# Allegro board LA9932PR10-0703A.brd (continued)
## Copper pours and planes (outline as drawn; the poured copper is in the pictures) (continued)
+VCHGR on BOTTOM (solid shape): 96.67,157.9 96.67,154.12 96.34,153.8 86.85,153.8 86.68,153.97 86.68,155.31 93.31,155.31 93.31,155.26 93.32,155.21 93.34,155.16 93.37,155.11 93.4,155.07 93.44,155.03 93.49,155 93.53,154.98 93.58,154.96 93.64,154.96 93.69,154.96 93.74,154.96 93.79,154.98 93.84,155 93.89,155.03 93.93,155.07 93.96,155.11 93.99,155.16 94,155.21 94.02,155.26 94.02,155.31 94.02,155.36 94,155.42 93.99,155.47 93.96,155.51 93.93,155.55 93.89,155.59 93.84,155.62 93.79,155.64 93.74,155.66 93.69,155.67 93.64,155.67 93.58,155.66 93.53,155.64 93.49,155.62 93.44,155.59 93.4,155.55 93.37,155.51 93.34,155.47 93.32,155.42 93.31,155.36 93.31,155.31 86.68,155.31 86.68,155.84 88.05,155.84 88.08,155.84 88.13,155.85 88.18,155.87 88.23,155.89 88.27,155.92 88.31,155.96 88.35,156 88.37,156.05 88.39,156.09 88.4,156.15 88.41,156.2 88.4,156.25 88.39,156.31 88.37,156.35 88.35,156.4 88.31,156.44 88.27,156.48 88.23,156.51 88.18,156.53 88.13,156.55 88.08,156.56 88.05,156.56 86.68,156.56 86.68,158.04 87.06,158.42 96.14,158.42
+VDISPLAY_VCC on TOP (solid shape): 13.33,201.72 13.33,200.34 13.26,200.27 12.2,200.27 12.02,200.44 12.02,201.64 12.15,201.77 13.28,201.77
+VDISPLAY_VCC on TOP (solid shape): 24.77,210.47 24.77,209.16 25.66,208.27 27.58,208.27 28.45,207.4 28.45,205.3 28.19,205.04 27.35,205.04 27.14,205.25 27.14,205.8 26.69,206.25 26.24,206.25 23.86,208.62 22.67,208.62 22.52,208.77 22.52,210.74 22.69,210.92 24.32,210.92
+VDISPLAY_VCC on BOTTOM (solid shape): 23.4,210.65 23.4,209.76 25.27,207.89 25.27,206.82 25.07,206.62 24.09,206.62 23.97,206.74 23.29,206.74 22.52,207.51 22.52,210.72 22.67,210.88 23.18,210.88
+VDISPLAY_VCC on IN2 (solid shape): 13.88,201.61 13.88,200.69 13.73,200.54 12.1,200.54 11.94,200.7 11.94,201.53 12.13,201.72 13.77,201.72
+VDISPLAY_VCC on IN2 (solid shape): 24.3,210.92 24.32,210.91 24.34,210.9 24.77,210.47 24.77,209.16 25.66,208.27 27.58,208.27 28.45,207.4 28.45,205.3 28.19,205.04 27.35,205.04 27.14,205.25 27.14,205.8 26.69,206.25 26.24,206.25 25.42,207.07 23.65,207.07 23.31,206.73 22.29,206.73 22.09,206.92 22.09,208.49 22.51,208.9 22.51,210.71 22.52,210.72 22.52,210.74 22.69,210.92
+VGA_B+ on TOP (solid shape): 17.08,157.98 17.08,155.5 16.77,155.18 11.24,155.18 10.86,155.57 10.86,157.03 11.18,157.34 15.37,157.34 16.16,158.14 16.92,158.14
+VGA_B+ on BOTTOM (solid shape): 4.89,162.49 4.89,161.47 5.08,161.28 6.73,161.28 7.69,160.33 7.69,156.01 8.26,155.44 10.54,155.44 10.86,155.76 10.86,157.09 11.11,157.34 15.56,157.34 15.94,157.72 15.94,159.44 16.13,159.63 16.77,159.63 16.96,159.44 16.96,154.61 13.08,150.74 4.89,150.74 3.08,152.55 3.08,154.64 3.05,154.68 3.05,156.01 4.28,157.24 4.29,157.25 4.32,157.28 4.32,157.9 4.33,157.92 4.84,157.92 4.84,158.62 4.33,158.62 4.33,159.12 4.84,159.12 4.84,159.82 4.33,159.82 4.33,161.01 4.13,161.22 4.13,162.49 4.19,162.55 4.83,162.55
+VGA_PCIE on TOP (solid shape): 86.78,128.82 88.36,128.82 88.49,128.69 88.49,127.99 88.43,127.93 86.29,127.93 85.57,128.66 85.57,129.61 85.69,129.73 85.86,129.73
+VGA_PCIE on BOTTOM (solid shape): 101.67,140.71 101.67,139.72 101.73,139.72 101.73,139.71 102.24,139.71 102.24,139.46 101.73,139.46 101.73,139.43 101.72,139.43 101.72,138.93 101.73,138.93 101.73,138.91 102.24,138.91 102.24,138.67 101.67,138.67 101.67,136.64 101.13,136.1 101.11,136.1 101.01,136.01 99.06,136.01 98.29,136.78 98.29,139.2 98.81,139.72 99.38,139.72 100.55,140.9 101.47,140.9
+VGA_PCIE on IN2 (solid shape): outline of 93 points within 74.77,129.07 79.16,135.91
+VGA_PCIE on VCC: 95.55,127.69 95.1,128.13 85.2,128.13 84.69,128.64 77.26,128.64 76.2,129.7 76.2,132.37 75.48,133.09 75.1,133.09 74.93,133.25 74.93,135.27 76.58,136.92 76.58,144.33 82.65,144.33 85,146.61 95.84,146.61 100.14,142.32 100.14,133.89 96.97,130.71 96.97,128.62 96.04,127.69
+VGA_PCIEP on TOP (solid shape): 105.79,139.75 105.79,138.17 105.48,137.85 103.91,137.85 103.9,137.86 103.9,140 103.91,140.01 105.54,140.01
+VGA_PCIEP on BOTTOM (solid shape): 108.97,140.93 108.97,138.35 108.78,138.16 105.92,138.16 105.6,137.85 104.89,137.85 104.89,137.85 103.83,137.85 103.83,137.85 101.98,137.85 101.86,137.98 101.86,138.53 102.37,138.53 102.37,139.03 101.86,139.03 101.86,139.33 102.37,139.33 102.37,139.83 101.86,139.83 101.86,140.26 101.92,140.33 103.44,140.33 103.76,140.01 103.83,140.01 104.89,140.01 104.9,140.01 106.23,141.34 108.55,141.34
-DCIN_JACK on BOTTOM (solid shape): 21.52,182.6 23.16,182.6 23.17,182.61 23.73,182.61 23.73,183.12 24.22,183.12 24.22,182.61 24.93,182.61 24.93,183.12 25.42,183.12 25.42,182.61 26.23,182.61 26.23,180.39 25.53,179.7 21.96,179.7 20.48,181.18 13.44,181.18 13.35,181.27 13.35,183.48 13.47,183.6 20.52,183.6
BOOT on TOP (solid shape): 55.96,164.02 55.96,162.97 55.89,162.9 55.41,162.9 54.99,162.49 54.04,162.49 53.85,162.68 52.77,162.68 52.71,162.74 52.71,162.87 52.77,162.93 54.81,162.93 55.15,163.27 55.15,163.99 55.24,164.07 55.49,164.07 55.49,164.07 55.91,164.07
BOOT1 on BOTTOM (solid shape): 126.24,142.04 126.24,141.34 126.27,141.31 126.27,141.29 126.33,141.13 126.49,141.07 126.51,141.07 127.32,140.26 127.32,139.25 127.26,139.18 126.42,139.18 126.32,139.28 126.32,140.93 126.24,141.02 125.99,141.28 125.99,142.04 126.05,142.1 126.18,142.1
BOOT1_1_VGA on TOP (solid shape): 27.31,154.3 27.31,153.6 27.94,152.96 27.94,152.39 27.81,152.26 27.12,152.26 26.54,152.83 26.54,154.23 26.67,154.36 27.24,154.36
BOOT1_VGA on TOP (solid shape): 27.94,151.63 27.94,150.99 27.81,150.87 27.56,150.87 27.5,150.8 27.43,150.8 27.43,150.74 26.73,150.04 26.7,150.03 26.69,150.04 26.5,150.06 26.33,149.98 25.21,149.98 25.15,150.04 25.15,150.1 25.27,150.23 26.16,150.23 26.74,150.8 26.74,151.5 26.93,151.69 27.88,151.69
BOOT2 on BOTTOM (solid shape): 122.56,143.18 123.45,143.18 123.51,143.12 123.51,143.06 123.45,142.99 122.62,142.99 122.37,142.74 121.49,142.74 121.48,142.74 121.29,142.55 121.29,142.54 121.29,142.29 121.22,142.23 120.72,142.23 120.65,142.29 120.65,143.18 120.72,143.25 122.49,143.25
BOOT2_2_VGA on TOP (solid shape): 21.46,154.74 21.46,154.17 21.4,154.1 19.31,154.1 19.24,154.17 19.24,154.74 19.37,154.87 21.34,154.87
BOOT2_VGA on TOP (solid shape): 20.26,153.41 20.26,151.88 20.45,151.69 20.47,151.67 21.42,151.67 21.48,151.61 21.48,150.74 21.42,150.68 21.33,150.68 20.96,151.06 20.13,151.06 19.31,151.88 19.31,153.41 19.37,153.47 20.19,153.47
BOOT_1.35V on TOP (solid shape): 173.36,87.56 173.36,86.99 173.58,86.76 174.4,86.76 174.5,86.67 175.58,86.67 175.64,86.6 175.64,86.54 175.58,86.48 172.91,86.48 172.4,86.99 172.4,87.49 172.53,87.62 173.29,87.62
BOOT_D on TOP (solid shape): 57.06,165.41 57.06,164.93 58.26,163.72 58.26,161.69 58.17,161.6 57.09,161.6 56.57,162.12 56.57,164.33 56.33,164.58 56.33,165.28 56.48,165.44 57.02,165.44
BQ24715_REGN on TOP (solid shape): 56.32,162.45 56.32,160 56.19,159.86 53.99,159.86 53.6,160.25 53.6,161.78 53.21,162.17 52.77,162.17 52.71,162.23 52.71,162.42 52.77,162.49 53.79,162.49 53.98,162.3 54.98,162.3 55.32,162.63 56.14,162.63
BST_3V on TOP (solid shape): 198.75,36.95 198.75,36.16 198.82,36.1 198.82,36.1 199.13,35.78 199.14,35.78 199.21,35.71 199.65,35.71 200.22,35.14 200.22,34.15 200.13,34.06 199.25,34.06 199.2,34.11 199.2,35.03 198.54,35.69 198.54,36.94 198.59,36.99 198.72,36.99
BST_5V on TOP (solid shape): 200.19,41.91 200.19,40.77 199.91,40.49 199.13,40.49 198.75,40.1 198.75,39.26 198.69,39.19 198.58,39.19 198.55,39.22 198.55,40.52 198.88,40.85 198.88,40.85 199,40.96 199,40.97 199.08,41.05 199.08,42.01 199.12,42.05 200.04,42.05
BST_+1.05VSP on TOP (solid shape): 175.13,94.73 175.13,94.54 174.75,94.16 174.75,92.51 174.69,92.45 174.18,92.45 174.12,92.51 174.12,94.48 174.44,94.8 175.07,94.8
CHAGER_SRC on BOTTOM (solid shape): outline of 158 points within 56.9,151.93 67.46,165.92
CHG_LGATE on TOP (solid shape): 64.14,161.98 64.14,160.9 63.95,160.71 63.12,160.71 62.74,161.09 62.74,161.98 62.93,162.17 63.95,162.17
CHG_LGATE on TOP (solid shape): 52.64,162.04 52.64,161.92 52.83,161.72 53.09,161.72 53.28,161.53 53.28,160.77 53.15,160.65 52.83,160.65 52.39,161.09 52.39,162.04 52.45,162.11 52.58,162.11
CHG_LGATE on TOP (solid shape): 64.07,156.27 64.07,155.36 63.79,155.09 63.79,151.84 63.62,151.67 62.95,151.67 62.86,151.76 62.86,155.16 62.8,155.21 62.8,156.25 62.97,156.42 63.93,156.42
CHG_LGATE on IN2 (solid shape): 64.01,161.41 64.01,155.3 63.87,155.15 62.96,155.15 62.8,155.31 62.8,160.45 62.61,160.65 61.91,160.65 61.53,161.03 61.53,161.66 61.6,161.72 63.69,161.72
CHG_LGATE on IN2 (solid shape): 54.51,161.72 54.68,161.69 54.84,161.72 57.09,161.72 57.34,161.47 57.34,160.9 57.02,160.58 52.96,160.58 52.71,160.84 52.71,161.47 52.96,161.72
CHG_PHASE on TOP (solid shape): 55.75,165.41 55.75,164.52 55.44,164.2 55.06,164.2 54.93,164.07 54.93,163.82 54.8,163.69 53.92,163.69 53.92,163.69 52.77,163.69 52.71,163.76 52.71,163.88 52.77,163.95 53.85,163.95 55.06,165.15 55.06,165.41 55.12,165.47 55.69,165.47
CHG_PHASE on TOP (solid shape): outline of 97 points within 64.77,153.69 72.14,165.98
CHG_PHASE on BOTTOM (solid shape): 74.8,165.28 74.8,157.47 74.8,157.47 74.8,156.75 74.3,156.25 69.9,156.25 69.67,156.48 69.67,156.9 69.42,157.15 68.43,157.15 68.25,157.33 68.25,160.17 68.42,160.33 69.53,160.33 69.79,160.59 69.79,162.23 69.28,162.74 68.45,162.74 68.26,162.93 68.26,165.72 68.45,165.91 74.17,165.91
CHG_PHASE on IN2 (solid shape): 56.01,164.46 56.01,163.95 55.76,163.69 53.98,163.69 53.91,163.76 53.91,164.07 53.98,164.14 54.55,164.14 54.99,164.58 55.88,164.58
CHG_PHASE on IN2 (solid shape): 70.22,164.32 70.22,163.45 70.08,163.31 68.73,163.31 68.59,163.45 68.59,164.28 68.77,164.46 70.08,164.46
CHG_UGATE on BOTTOM (solid shape): 69.53,156.33 69.53,155.29 69.35,155.11 68.05,155.11 67.91,155.25 67.91,156.05 68.38,156.52 69.34,156.52
CHG_UGATE on BOTTOM (solid shape): 69.6,161.88 69.6,161 69.43,160.84 68.65,160.84 68.26,161.22 68.26,161.92 68.45,162.11 69.37,162.11
CHG_UGATE on IN2 (solid shape): 69.57,161.18 69.57,155.38 69.28,155.09 68.03,155.09 67.89,155.22 67.89,156.12 68.2,156.43 68.2,160.33 68.07,160.45 67.38,160.45 67.18,160.65 67.18,161.09 67.44,161.34 69.41,161.34
CHG_UGATE on IN2 (solid shape): 54.1,163.55 54.2,163.57 54.59,163.57 54.69,163.55 54.78,163.57 55.73,163.57 55.82,163.57 56.07,163.31 56.07,162.87 55.95,162.74 55.25,162.74 54.87,163.12 53.91,163.12 53.85,163.19 53.85,163.44 53.98,163.57
CPU_B+ on TOP (solid shape): 123.06,140.28 123.26,140.22 123.45,140.28 124.18,140.28 124.61,139.85 127.09,139.85 130.97,135.97 133.95,135.97 134.48,135.44 134.48,132.48 134.09,132.09 130.27,132.09 128.76,133.59 128.76,134.56 126.05,137.27 118.5,137.27 118.17,136.95 118.17,135.25 118.13,135.21 114.05,135.21 113.41,135.85 113.41,139.71 113.98,140.28
CPU_B+ on BOTTOM (solid shape): 131.13,136.55 134.84,136.55 135,136.39 135,132.03 134.75,131.78 128.8,131.78 128.64,131.94 128.64,136.57 128.97,136.9 130.78,136.9
CPU_B+ on BOTTOM (solid shape): outline of 231 points within 98.13,131.9 118.24,157.72
CPU_B+ on IN3 (solid shape): outline of 121 points within 113.41,132.01 133.13,139.79
DH_1.35V on TOP (solid shape): 161.61,88 161.61,87.11 161.42,86.92 160.46,86.92 160.25,87.13 160.25,88.05 160.44,88.24 161.37,88.24
DH_1.35V on TOP (solid shape): 174.75,87.11 175.58,87.11 175.64,87.05 175.64,86.92 175.58,86.86 174.5,86.86 174.44,86.92 173.74,86.92 173.61,87.05 173.61,87.64 173.72,87.75 174.12,87.75
DH_1.35V on IN1 (solid shape): 161.86,88.19 161.86,87.3 161.48,86.92 160.62,86.92 160.5,87.05 160.5,88.16 160.85,88.51 161.55,88.51
DH_1.35V on IN1 (solid shape): 174.56,87.24 174.56,87.11 174.44,86.99 171.96,86.99 171.39,87.56 171.39,87.87 171.58,88.06 173.74,88.06
DL_1.35V on TOP (solid shape): 166.88,87.11 166.88,86.22 166.69,86.03 165.8,86.03 165.61,86.22 165.61,87.18 165.74,87.3 166.69,87.3
DL_1.35V on TOP (solid shape): 175.8,88.6 175.93,88.6 176.02,88.51 176.02,87.75 175.96,87.68 175.9,87.68 174.75,88.83 174.75,89.14 174.94,89.33 175.07,89.33
DL_1.35V on IN4 (solid shape): 167.07,88.7 167.07,87.11 166.75,86.79 165.93,86.79 165.74,86.99 165.74,88.7 165.99,88.95 166.82,88.95
DL_1.35V on IN4 (solid shape): 175.64,88.83 175.64,88.51 175.52,88.38 173.67,88.38 173.48,88.57 173.48,89.21 173.67,89.4 175.07,89.4
EXT_MIC on TOP (solid shape): 286.01,154.68 286.01,153.92 286.22,153.71 287.14,153.71 287.32,153.53 288.95,153.53 289.04,153.63 289.8,153.63 290.25,153.18 290.25,152.76 289.88,152.39 286.51,152.39 286.2,152.71 285.37,152.71 284.78,153.29 284.58,153.29 284.55,153.3 284.48,153.38 284.48,153.92 284.86,153.92 285.14,154.2 285.14,154.59 285.3,154.75 285.94,154.75
EXT_MIC on IN1 (solid shape): 291.07,154.26 291.07,153.79 289.72,152.44 289.43,152.44 288.72,153.14 288.72,153.27 289.15,153.69 289.15,154.18 289.98,155.01 290.32,155.01
INT_SPK_L+ on TOP (solid shape): 273.12,162.8 273.12,161.98 272.92,161.79 272.92,160.39 272.86,160.33 272.73,160.33 272.67,160.39 272.67,162.87 272.73,162.93 272.99,162.93
INT_SPK_L+ on TOP (solid shape): 179.19,15.62 179.19,12.79 179.15,12.75 178.15,12.75 178.08,12.82 178.08,13.67 178.25,13.83 178.25,15.6 178.43,15.79 178.48,15.83 178.98,15.83
INT_SPK_L+ on IN4 (solid shape): 179.26,15.67 179.26,13.58 178.94,13.26 178.56,13.26 178.25,13.58 178.25,15.74 178.31,15.8 179.14,15.8
INT_SPK_L+ on IN4 (solid shape): 273.37,162.68 273.37,160.84 273.18,160.65 272.48,160.65 272.23,160.9 272.23,161.92 272.35,162.04 272.35,162.49 272.73,162.87 273.18,162.87
INT_SPK_L- on TOP (solid shape): 180.34,15.55 180.34,13.88 180.66,13.56 180.66,12.79 180.62,12.76 179.55,12.76 179.46,12.85 179.46,15.62 179.64,15.8 180.09,15.8
INT_SPK_L- on TOP (solid shape): 272.42,162.87 272.42,160.39 272.35,160.33 272.23,160.33 272.16,160.39 272.16,161.48 272.16,161.49 272.18,161.6 272.16,161.7 272.16,161.71 272.16,161.92 272.1,161.98 271.72,161.98 271.62,162.08 271.62,162.92 271.7,162.99 272.29,162.99
INT_SPK_L- on IN4 (solid shape): 180.53,15.61 180.53,14.91 180.98,14.47 180.98,14.02 180.6,13.64 180.28,13.64 179.58,14.34 179.58,15.61 179.71,15.74 180.41,15.74
INT_SPK_L- on IN4 (solid shape): 272.1,162.87 272.1,162.59 272.1,162.17 271.92,161.99 271.91,161.98 271.89,161.98 270.45,161.98 270.26,162.17 270.26,162.8 270.45,162.99 271.97,162.99
INT_SPK_R+ on TOP (solid shape): 272.8,165.15 272.8,164.58 272.54,164.33 271.21,164.33 270.89,164.01 270.89,163.57 270.83,163.5 270.7,163.5 270.64,163.57 270.64,164.39 271.59,165.34 272.61,165.34
INT_SPK_R+ on TOP (solid shape): 183.01,15.61 183.01,13.67 182.84,13.5 182.84,12.81 182.81,12.78 181.78,12.78 181.74,12.81 181.74,13.5 182.12,13.88 182.12,14.32 182.12,14.32 182.12,15.61 182.25,15.74 182.88,15.74
INT_SPK_R+ on IN4 (solid shape): 183.07,16.55 183.07,14.79 182.95,14.66 182.31,14.66 182.18,14.79 182.18,16.49 182.33,16.64 182.99,16.64
INT_SPK_R+ on IN4 (solid shape): 272.73,165.22 272.73,164.71 272.54,164.52 272.33,164.52 272.33,164.52 271.09,164.52 270.89,164.71 270.26,164.71 270.13,164.84 270.13,165.34 270.32,165.53 272.42,165.53
INT_SPK_R- on TOP (solid shape): 184.28,15.48 184.28,12.81 184.26,12.78 183.24,12.78 183.21,12.82 183.21,13.42 183.26,13.48 183.26,15.55 183.45,15.74 184.02,15.74
INT_SPK_R- on TOP (solid shape): 272.35,164.01 272.35,163.31 272.29,163.25 271.59,163.25 271.4,163.06 271.4,162.74 271.34,162.68 271.22,162.68 271.19,162.69 271.17,162.73 271.17,163.93 271.32,164.07 272.29,164.07
INT_SPK_R- on IN4 (solid shape): 184.47,16.31 184.47,15.04 184.09,14.66 183.58,14.66 183.39,14.85 183.39,16.33 183.6,16.54 184.23,16.54
INT_SPK_R- on IN4 (solid shape): 270.51,164.26 270.68,164.24 270.86,164.26 270.86,164.26 272.23,164.26 272.35,164.14 272.35,163.38 272.23,163.25 272.08,163.25 270.32,163.25 270.19,163.38 270.19,164.2 270.26,164.26 270.5,164.26
INT_SPKL_L+ on TOP (solid shape): 179.26,12.18 179.26,10.4 179.2,10.34 178.25,10.34 178.06,10.53 178.06,12.25 178.12,12.31 179.14,12.31
INT_SPKL_L+ on BOTTOM (solid shape): 179.71,11.23 179.71,8.82 178.75,8.82 178.75,11.23 178.88,11.36 179.58,11.36
INT_SPKL_L- on TOP (solid shape): 180.72,12.18 180.72,11.48 181.12,11.09 181.12,10.57 180.89,10.34 179.64,10.34 179.55,10.44 179.55,12.21 179.64,12.31 180.6,12.31
INT_SPKL_L- on BOTTOM (solid shape): 180.98,11.23 180.98,8.82 180.09,8.82 180.09,11.23 180.28,11.42 180.79,11.42
INT_SPKR_R+ on TOP (solid shape): 182.88,12.25 182.88,10.66 182.44,10.21 181.8,10.21 181.61,10.4 181.61,12.25 181.68,12.31 182.82,12.31
INT_SPKR_R+ on BOTTOM (solid shape): 182.37,11.23 182.37,8.82 181.36,8.82 181.36,11.17 181.55,11.36 182.25,11.36
INT_SPKR_R- on TOP (solid shape): 184.34,12.19 184.34,11.46 184.66,11.14 184.66,10.53 184.34,10.21 183.39,10.21 183.2,10.4 183.2,12.22 183.24,12.26 184.27,12.26
INT_SPKR_R- on BOTTOM (solid shape): 184.15,11.1 184.15,10.53 183.45,9.83 183.45,8.82 182.63,8.82 182.63,10.47 183.52,11.36 183.9,11.36
LG_3V on TOP (solid shape): 207.3,34.81 207.3,34.45 207.2,34.34 206.38,34.34 205.93,33.9 205.42,33.9 205.23,34.09 205.23,34.79 205.36,34.92 207.2,34.92
LG_3V on TOP (solid shape): 201.52,36.95 201.52,36.41 201.3,36.19 200.47,36.19 200.28,36.38 200.28,36.95 200.05,37.18 199.67,37.18 199.4,37.18 199.35,37.23 199.35,37.38 199.39,37.43 201.04,37.43
LG_5V on TOP (solid shape): 204.73,44.31 204.73,44.12 203.9,43.3 203.9,43.04 203.77,42.92 203.01,42.92 202.88,43.04 202.88,43.68 203.65,44.44 204.6,44.44
LG_5V on TOP (solid shape): 201.3,40.24 201.3,39.43 200.83,38.95 200.44,38.95 200.25,38.76 199.39,38.76 199.35,38.81 199.35,38.99 199.39,39.03 199.9,39.03 200.1,39.23 200.1,40.19 200.53,40.63 200.92,40.63
LG_+1.05VSP on TOP (solid shape): 165.74,100.19 165.74,99.37 165.61,99.24 164.78,99.24 164.66,99.37 164.66,100.26 164.72,100.32 165.61,100.32
LG_+1.05VSP on IN2 (solid shape): 166.94,100.07 166.94,99.24 166.82,99.11 164.91,99.11 164.72,99.3 164.72,100.13 164.91,100.32 166.69,100.32
LG_+1.05VSP on IN2 (solid shape): 175.2,97.65 175.2,97.08 175.07,96.95 173.04,96.95 172.72,97.27 172.72,97.91 172.91,98.1 174.75,98.1
LGATE1 on BOTTOM (solid shape): 125,142.06 125,141.12 124.97,141.09 124.97,140.13 124.84,140.01 124.65,140.01 124.53,140.13 124.53,140.9 124.78,141.15 124.78,142.04 124.84,142.1 124.96,142.1
LGATE1 on BOTTOM (solid shape): 128.62,131.25 128.62,129.83 128.38,129.59 128.02,129.59 127.83,129.77 127.83,130.69 127.55,130.97 127.23,130.97 127.07,131.13 127.07,131.42 127.23,131.58 128.29,131.58
LGATE1 on IN2 (solid shape): 128.14,132.64 128.14,131.18 127.95,130.99 127.26,130.99 127.07,131.18 127.07,132.71 127.19,132.83 127.95,132.83
LGATE1 on IN2 (solid shape): 124.97,140.96 124.97,139.69 125.1,139.56 125.1,138.8 125.03,138.74 124.21,138.74 124.08,138.86 124.08,139.69 124.53,140.13 124.53,141.02 124.59,141.09 124.84,141.09
LGATE1_VGA on TOP (solid shape): 24.42,152.83 24.42,152.04 24.29,151.92 24.29,150.74 24.23,150.68 24.13,150.68 24.07,150.74 24.07,151.88 23.94,152.01 23.94,152.83 24.07,152.96 24.28,152.96
LGATE1_VGA on BOTTOM (solid shape): 23.5,162.11 23.5,161.66 23.31,161.47 21.53,161.47 21.34,161.66 21.34,162.17 21.53,162.36 23.24,162.36
LGATE1_VGA on IN1 (solid shape): 23.62,161.92 23.62,160.52 23.5,160.39 22.54,160.39 22.42,160.52 22.42,161.98 22.61,162.17 23.37,162.17
LGATE1_VGA on IN1 (solid shape): 24.64,154.36 24.64,153.22 24.39,152.96 24.39,152.01 24.26,151.88 24.13,151.88 23.94,152.07 23.94,152.9 23.75,153.09 23.75,154.23 24,154.49 24.51,154.49
LGATE2 on BOTTOM (solid shape): 123.54,130.7 123.54,129.73 123.4,129.59 122.42,129.59 122.29,129.72 122.29,130.67 122.48,130.86 123.37,130.86
LGATE2 on BOTTOM (solid shape): 123.83,142.04 123.83,141.21 123.51,140.9 123.51,140.45 123.38,140.33 123.19,140.33 123,140.52 123,141.21 123.57,141.79 123.57,142.04 123.64,142.1 123.76,142.1
LGATE2 on IN4 (solid shape): 123.57,132.07 123.57,129.86 123.38,129.67 122.77,129.67 122.56,129.88 122.56,132.08 122.75,132.26 123.38,132.26
LGATE2 on IN4 (solid shape): 123.51,141.21 123.51,140.33 123.57,140.26 123.57,139.06 123.32,138.8 122.68,138.8 122.49,138.99 122.49,139.88 123,140.39 123,141.21 123.19,141.4 123.32,141.4
LGATE2_VGA on TOP (solid shape): 23.31,152.83 23.31,152.01 23.12,151.82 23.12,150.74 23.05,150.68 22.93,150.68 22.86,150.74 22.86,152.01 22.83,152.04 22.82,152.06 22.82,152.08 22.82,152.17 22.8,152.26 22.8,152.27 22.8,152.59 22.8,152.6 22.82,152.7 22.81,152.81 22.81,152.84 22.82,152.86 22.93,152.96 23.18,152.96
LGATE2_VGA on BOTTOM (solid shape): 9.34,163.12 9.34,161.98 9.15,161.79 9.14,161.79 9.09,161.74 8.5,161.74 8.26,161.98 8.26,163.12 8.45,163.31 9.15,163.31
LGATE2_VGA on IN2 (solid shape): 10.73,162.99 10.73,162.17 10.59,162.03 8.45,162.03 8.26,162.22 8.26,163.1 8.41,163.25 10.48,163.25
LGATE2_VGA on IN2 (solid shape): 23.31,154.42 23.31,152.14 23.12,151.95 22.93,151.95 22.83,152.04 22.82,152.06 22.82,152.08 22.82,152.17 22.8,152.26 22.8,152.27 22.8,152.59 22.8,152.6 22.82,152.72 22.8,152.85 22.8,152.85 22.8,153.53 22.23,154.1 22.23,154.61 22.54,154.93 22.8,154.93
LX_PCIE on BOTTOM (solid shape): 108.97,137.63 108.97,135.94 108.71,135.69 107.95,135.69 107.57,135.31 107.57,133.81 107.49,133.73 105.53,133.73 104.64,134.61 104.64,135.81 105.79,136.96 105.79,137.55 106.07,137.82 108.78,137.82
Net_10 on BOTTOM (solid shape): 299.85,155.45 299.73,155.16 299.69,154.85 299.69,150.44 299.45,149.88 298.89,149.65 295.59,149.65 294.99,149.49 294.26,148.76 293.86,148.65 293.59,148.65 293.59,150.44 293.59,152.45 294.47,154.57 296.59,155.45 298.62,155.45
Net_11 on TOP (solid shape): 299.85,155.45 299.73,155.16 299.69,154.85 299.69,150.44 299.45,149.88 298.89,149.65 295.59,149.65 294.99,149.49 294.26,148.76 293.86,148.65 293.59,148.65 293.59,150.44 293.59,152.45 294.47,154.57 296.59,155.45 298.62,155.45
PCIE_B+ on BOTTOM (solid shape): 105.73,131.56 105.74,131.55 107.49,131.55 107.57,131.47 107.57,130.67 106.75,129.85 104.92,129.85 104.87,129.8 104.35,129.8 104.35,129.27 104.1,129.27 104.1,129.8 103.55,129.8 103.55,129.27 103.3,129.27 103.3,129.8 102.86,129.8 102.74,129.91 102.74,131.63 103.06,131.94 105.35,131.94
PH2_VGA on TOP (solid shape): 21.53,153.34 21.53,153.22 21.78,152.96 21.97,152.96 22.1,152.84 22.1,152.02 22.1,152.01 22.22,151.88 22.27,151.84 22.29,151.82 22.29,150.74 22.23,150.68 22.14,150.68 22.07,150.74 22.07,151.61 21.66,152.03 21.66,152.39 21.53,152.52 20.58,152.52 20.45,152.64 20.45,153.41 20.51,153.47 21.4,153.47
PH2_VGA on BOTTOM (solid shape): 9.34,156.96 9.34,155.88 9.21,155.76 8.38,155.76 8.26,155.88 8.26,157.04 8.47,157.26 9.04,157.26
PH2_VGA on IN2 (solid shape): 9.34,157.28 9.34,155.84 9.21,155.71 8.38,155.71 8.26,155.83 8.26,157.34 8.45,157.53 9.08,157.53
PH2_VGA on IN2 (solid shape): 22.1,153.22 22.1,151.96 22.04,151.9 21.75,151.9 21.66,151.99 21.66,152.07 21.66,152.07 21.66,152.39 20.51,153.53 20.51,153.91 20.7,154.1 21.21,154.1
PHASE1 on TOP (solid shape): 129.48,129.15 129.48,127.94 129.29,127.75 128.53,127.75 128.4,127.88 128.4,129.21 128.46,129.28 129.35,129.28
PHASE1 on BOTTOM (solid shape): 135.19,130.8 135.19,124.58 134.81,124.2 133.17,124.2 132.9,124.46 132.9,126.14 132.37,126.14 132.37,124.35 132.22,124.2 123.97,124.2 123.76,124.41 123.76,128.89 124.08,129.21 128.27,129.21 128.56,129.5 131.08,129.5 131.52,129.94 131.52,130.94 131.76,131.18 134.81,131.18
PHASE1 on BOTTOM (solid shape): 125.41,142.04 125.41,141.09 125.54,140.96 125.54,140.13 125.67,140 125.8,139.88 126.05,139.88 126.11,139.82 126.11,139.25 126.05,139.18 125.22,139.18 125.1,139.31 125.1,140.08 125.1,140.15 125.11,140.25 125.1,140.34 125.1,140.74 125.11,140.81 125.11,140.88 125.1,140.9 125.16,140.96 125.16,142.04 125.22,142.1 125.35,142.1
PHASE1 on IN4 (solid shape): 129.41,130.67 129.41,128.9 129.35,128.83 128.53,128.83 128.4,128.96 128.4,130.67 128.46,130.74 129.35,130.74
PHASE1 on IN4 (solid shape): 125.54,140.96 125.54,140.07 125.8,139.82 125.8,139.18 125.59,138.98 125.02,138.98 124.81,139.18 124.81,139.79 125.1,140.07 125.1,140.15 125.11,140.25 125.1,140.35 125.1,140.74 125.11,140.81 125.11,140.88 125.1,140.9 125.29,141.09 125.41,141.09
PHASE1_VGA on TOP (solid shape): 25.91,154.3 25.91,152.07 25.08,151.25 25.08,150.74 25.03,150.68 24.93,150.68 24.87,150.74 24.87,151.61 25.15,151.88 25.15,152.89 25.15,154.3 25.21,154.36 25.85,154.36
PHASE1_VGA on BOTTOM (solid shape): 26.8,160.77 26.8,157.09 26.29,156.58 23.37,156.58 23.24,156.71 23.24,157.22 23.05,157.41 21.66,157.41 21.34,157.72 21.34,160.71 21.59,160.96 26.61,160.96
PHASE1_VGA on IN2 (solid shape): 26.15,157.71 26.15,155.5 26.07,155.42 25.16,155.42 25.03,155.55 25.03,157.88 25.28,158.13 25.74,158.13
PHASE1_VGA on IN2 (solid shape): 26.12,154.47 26.12,152.14 25.87,151.89 25.42,151.89 25.18,152.12 25.18,153.24 25,153.42 25,154.52 25.09,154.6 25.99,154.6
PHASE2 on TOP (solid shape): 115.38,129.72 115.38,128.91 115.38,128.83 115.32,128.77 113.54,128.77 113.29,129.02 113.29,129.72 113.41,129.85 115.25,129.85
PHASE2 on BOTTOM (solid shape): 123.51,142.29 123.51,142.17 122.37,141.02 120.72,141.02 120.59,141.15 120.59,141.91 120.65,141.98 121.86,141.98 121.86,141.98 122.36,141.98 122.49,142.11 122.53,142.15 122.8,142.42 123.38,142.42
PHASE2 on BOTTOM (solid shape): 116.67,130.97 116.67,129.76 117.6,128.83 122.7,128.83 122.99,128.54 122.99,124.31 122.88,124.2 115.13,124.2 114.68,124.64 114.68,126.16 114.49,126.36 114.24,126.36 114.11,126.23 114.11,125.78 113.92,125.59 113.16,125.59 112.59,126.16 112.59,128.07 113.05,128.53 113.05,129.42 113.44,129.81 113.44,130.95 113.67,131.18 116.46,131.18
PHASE2 on IN2 (solid shape): 114.49,130.74 114.49,129.21 114.37,129.09 113.54,129.09 113.35,129.28 113.35,130.74 113.48,130.86 114.37,130.86
PHASE2 on IN2 (solid shape): 123.06,141.85 123.06,141.66 122.62,141.21 122.62,140.9 121.73,140.01 121.48,140.01 121.03,140.45 121.03,140.77 121.76,141.5 121.76,141.63 122.11,141.98 122.94,141.98
PHASE2_VGA on BOTTOM (solid shape): 14.99,168.01 14.99,166.82 14.93,166.76 14.6,166.76 14.51,166.66 14.51,166.36 14.61,166.26 14.91,166.26 14.99,166.18 14.99,164.77 15.37,164.39 15.37,162.36 14.8,161.79 14.8,161.78 14.78,161.74 14.75,161.72 9.91,161.72 9.65,161.98 9.65,163.82 9.4,164.07 9.4,166.17 11.5,168.27 14.73,168.27
RING2 on TOP (solid shape): 284.16,158.57 284.16,157.99 284.37,157.78 284.37,157.45 284.3,157.37 284.06,157.37 284.04,157.34 282.89,157.34 282.71,157.52 282.71,158.55 282.8,158.63 284.1,158.63
RING2 on TOP (solid shape): 277.32,155.98 277.32,155.51 277.13,155.33 276.41,155.33 276,155.73 275.67,155.73 275.56,155.85 274.71,155.85 274.64,155.91 274.64,156.01 274.7,156.07 274.73,156.1 277.19,156.1
RING2 on IN3 (solid shape): 278.87,156.35 278.87,155.03 278.75,154.91 276.11,154.91 275.61,155.42 275.61,156.01 275.88,156.29 277.55,156.29 277.72,156.46 278.75,156.46
RING2 on IN3 (solid shape): 284.42,158.08 284.42,156.99 284.18,156.75 282.45,156.75 281.49,155.78 280.51,156.77 280.51,156.98 281.21,157.68 281.31,157.68 281.93,158.3 284.2,158.3
RING2_L on TOP (solid shape): 301.63,165.66 301.63,164.52 301.28,164.17 299.18,164.17 298.9,164.46 298.9,165.6 299.28,165.98 301.31,165.98
RING2_L on TOP (solid shape): 290.05,160.34 290.05,159.98 287.48,157.41 286.3,157.41 286.17,157.55 284.99,157.55 284.53,158.01 284.53,158.85 284.86,159.18 286.64,159.18 287.85,160.39 288.21,160.39 288.94,161.13 289.26,161.13
SLEEVE on TOP (solid shape): 277.29,156.8 277.29,156.59 277.06,156.36 274.7,156.36 274.64,156.41 274.64,156.52 274.72,156.6 275.44,156.6 275.66,156.83 275.66,156.92 275.82,157.08 277,157.08
SLEEVE on TOP (solid shape): 284.85,155.38 284.85,154.28 284.75,154.17 284.22,154.17 284.12,154.07 284.12,153.41 284.02,153.31 282.65,153.31 282.51,153.45 282.51,153.92 282.89,154.3 282.89,154.74 282.9,154.74 282.9,154.9 282.9,154.91 282.9,155.26 283.2,155.55 284.69,155.55
SLEEVE on IN2 (solid shape): 284.83,154.75 284.83,153.99 284.39,153.55 282.83,153.55 282.7,153.68 282.7,154.99 282.9,155.19 284.39,155.19
SLEEVE on IN2 (solid shape): 279.34,156.66 279.34,156.39 278.39,155.44 278.24,155.44 277.27,156.42 275.77,156.42 275.6,156.59 275.6,157.64 275.7,157.74 278.26,157.74
SNUB_1.05V on TOP (solid shape): 164.28,102.35 164.28,100.76 164.15,100.64 163.13,100.64 163.07,100.7 163.07,101.46 162.69,101.84 161.87,101.84 161.68,102.03 161.68,102.61 161.8,102.73 163.9,102.73
SNUB_1.35V on TOP (solid shape): 164.28,81.21 164.28,79.62 164.21,79.56 163.2,79.56 162.43,80.32 162.12,80.32 162.05,80.38 162.05,81.27 162.12,81.33 164.15,81.33
SNUB_3V on TOP (solid shape): 206,33.65 206.95,33.65 207.01,33.58 207.01,32.69 206.95,32.63 204.09,32.63 204.03,32.69 204.03,33.71 204.09,33.77 205.87,33.77
SNUB_5V on TOP (solid shape): 206.32,43.08 206.32,42.16 206.22,42.07 205.37,42.07 205.17,41.87 205.17,41.52 205.11,41.46 204.09,41.46 204.03,41.52 204.03,43.11 204.09,43.17 206.23,43.17
SNUB_CHARGER on TOP (solid shape): 66.04,154.8 66.04,153.85 65.15,152.96 64.07,152.96 63.95,153.09 63.95,154.74 64.14,154.93 65.91,154.93
SNUB_GPU_P1 on BOTTOM (solid shape): 23.05,156.77 23.05,156.2 23.31,155.95 24.39,155.95 24.45,155.88 24.45,155.25 24.39,155.18 21.91,155.18 21.72,155.37 21.72,156.77 21.85,156.9 22.93,156.9
SNUB_GPU_P2 on BOTTOM (solid shape): 8.73,165.32 8.73,164.32 8.61,164.2 6.01,164.2 5.87,164.34 5.87,165.23 6.05,165.41 8.64,165.41
SNUB_V1 on TOP (solid shape): 128.72,130.67 128.72,129.59 128.65,129.53 128.08,129.53 127.89,129.34 127.89,127.88 127.76,127.75 127.13,127.75 127,127.88 127,130.67 127.07,130.74 128.65,130.74
SNUB_V2 on TOP (solid shape): 117.35,131.18 117.35,129.02 117.03,128.7 115.76,128.7 115.51,128.96 115.51,131.18 115.64,131.31 117.22,131.31
SW1 on TOP (solid shape): 198.85,41.98 198.85,41.07 198.35,40.56 198.35,39.23 198.3,39.19 198.18,39.19 198.14,39.23 198.14,40.23 197.55,40.82 197.55,41.19 197.72,41.36 197.72,41.94 197.83,42.04 198.79,42.04
SW1 on TOP (solid shape): 209.04,49.27 209.04,47.36 210.31,46.09 213.74,46.09 214.12,45.71 214.12,42.54 213.93,42.34 208.04,42.34 207.74,42.04 206.95,42.04 206.88,42.1 206.88,43.36 206.44,43.81 205.61,43.81 205.36,44.06 205.36,46.85 206.57,48.06 206.57,49.58 206.69,49.71 208.6,49.71
SW1 on IN2 (solid shape): 199.65,41.65 199.65,41.01 199.39,40.76 197.68,40.76 197.55,40.88 197.55,41.27 197.74,41.46 198.69,41.46 199.01,41.77 199.52,41.77
SW1 on IN2 (solid shape): 207.27,47.3 207.27,46.66 206.31,45.71 205.93,45.71 205.55,46.09 205.55,46.47 206.12,47.04 206.12,47.3 206.25,47.42 207.14,47.42
SW2 on TOP (solid shape): 198.35,36.94 198.35,35.68 198.89,35.13 198.89,34.11 198.81,34.03 197.99,34.03 197.89,34.12 197.89,34.72 197.57,35.05 197.57,35.34 198.14,35.92 198.14,36.94 198.19,36.99 198.3,36.99
SW2 on TOP (solid shape): 213.62,39.82 213.62,39.61 213.64,39.59 213.64,34.38 213.03,33.77 208.76,33.77 208.41,33.42 208.41,32.69 208.35,32.63 207.71,32.63 207.65,32.69 207.65,33.76 207.9,34.01 207.9,36.88 209.15,38.14 209.15,40.05 209.26,40.15 213.28,40.15
SW2 on IN2 (solid shape): 199.52,34.92 199.52,34.34 199.26,34.09 198.82,34.09 198.06,34.85 197.74,34.85 197.55,35.04 197.55,35.36 197.68,35.49 198.95,35.49
SW2 on IN2 (solid shape): 209.87,34.28 209.87,33.9 209.62,33.65 208.54,33.65 208.28,33.39 207.84,33.39 207.65,33.58 207.65,34.22 207.84,34.41 209.74,34.41
SW_1.35V on TOP (solid shape): 174.59,90.32 174.59,88.79 175.64,87.75 175.64,87.37 175.58,87.3 174.75,87.3 173.86,88.19 173.86,90.29 173.93,90.35 174.56,90.35
SW_1.35V on TOP (solid shape): 161.55,91.87 161.55,89.01 161.31,88.76 160.15,88.76 159.96,88.57 159.96,86.99 160.21,86.73 164.66,86.73 164.83,86.56 164.83,82.51 164.73,82.41 162.18,82.41 161.67,81.91 161.67,80.57 161.48,80.38 158.5,80.38 157.99,80.89 157.99,91.94 158.12,92.07 161.36,92.07
SW_1.35V on BOTTOM (solid shape): 164.53,91.75 164.53,84.45 164.09,84 158.43,84 158.18,84.25 158.18,87.2 160.35,87.2 160.35,87.15 160.36,87.1 160.38,87.04 160.4,87 160.43,86.95 160.47,86.91 160.51,86.88 160.56,86.85 160.61,86.83 160.66,86.82 160.71,86.82 160.77,86.82 160.82,86.84 160.87,86.86 160.91,86.88 160.97,86.92 161,86.93 161.03,86.92 161.09,86.88 161.13,86.86 161.18,86.84 161.23,86.82 161.29,86.82 161.34,86.82 161.39,86.83 161.44,86.85 161.49,86.88 161.53,86.91 161.57,86.95 161.6,87 161.62,87.04 161.64,87.1 161.65,87.15 161.65,87.2 161.64,87.26 161.62,87.31 161.6,87.36 161.57,87.4 161.53,87.44 161.49,87.47 161.44,87.5 161.39,87.52 161.34,87.53 161.29,87.53 161.23,87.53 161.18,87.51 161.13,87.49 161.09,87.47 161.03,87.43 161,87.43 160.97,87.43 160.91,87.47 160.87,87.49 160.82,87.51 160.77,87.53 160.71,87.53 160.66,87.53 160.61,87.52 160.56,87.5 160.51,87.47 160.47,87.44 160.43,87.4 160.4,87.36 160.38,87.31 160.36,87.26 160.35,87.2 158.18,87.2 158.18,91.37 158.88,92.07 164.22,92.07
SW_1.35V on IN1 (solid shape): 175.33,88 175.33,87.81 175.2,87.68 174.44,87.68 173.86,88.26 172.79,88.26 172.53,88.51 172.53,89.08 172.79,89.33 173.99,89.33
SW_1.35V on IN1 (solid shape): 161.23,89.53 161.23,88.83 161.1,88.7 159.77,88.7 159.51,88.45 159.07,88.45 158.94,88.57 158.94,89.46 159.07,89.59 160.09,89.59 160.21,89.72 161.04,89.72
SW_+1.05VSP on TOP (solid shape): 174.31,95.81 175.07,95.81 175.13,95.75 175.13,95.62 175.07,95.56 174.31,95.56 174.21,95.46 173.2,95.46 172.85,95.11 172.02,95.11 171.96,95.18 171.96,95.81 172.05,95.91 174.21,95.91
SW_+1.05VSP on TOP (solid shape): 162.75,101.15 162.75,100.32 163.2,99.88 163.96,99.88 164.15,99.69 164.15,96.19 163.96,96 163.2,96 162.94,95.75 162.94,94.16 162.85,94.07 161.26,94.07 160.66,94.67 160.66,100.83 161.16,101.34 162.56,101.34
SW_+1.05VSP on BOTTOM (solid shape): 165.74,97.78 165.74,94.03 165.67,93.97 161.23,93.97 160.72,94.48 160.72,98.03 160.91,98.22 165.29,98.22
SW_+1.05VSP on IN2 (solid shape): 164.59,96.89 164.59,96.32 164.34,96.07 163.07,96.07 162.94,96.19 162.94,97.02 163.07,97.15 164.34,97.15
SW_+1.05VSP on IN2 (solid shape): 173.36,96 173.86,96 174.06,95.81 174.06,95.56 173.99,95.49 171.77,95.49 171.58,95.68 171.58,96.26 171.83,96.51 172.85,96.51
UG_3V on TOP (solid shape): 210.31,41.33 210.31,40.63 210.08,40.4 209.27,40.4 209.14,40.53 209.14,41.29 209.3,41.46 210.19,41.46
UG_3V on TOP (solid shape): 199.85,36.94 199.85,36.04 199.71,35.91 199.19,35.91 198.94,36.15 198.94,36.93 199.07,37.05 199.74,37.05
UG_3V on IN2 (solid shape): 200.47,37.65 200.47,37.14 199.84,36.5 199.84,36.06 199.65,35.87 199.33,35.87 199.2,35.99 199.2,37.26 199.77,37.84 200.28,37.84
UG_3V on IN2 (solid shape): 210.31,41.33 210.31,40.95 210.12,40.76 209.23,40.76 208.85,40.38 208.35,40.38 208.22,40.5 208.22,41.27 208.41,41.46 210.19,41.46
UG_5V on TOP (solid shape): 208.92,50.28 208.92,50.03 208.79,49.9 206.69,49.9 206.57,50.03 206.57,50.28 206.69,50.41 208.79,50.41
UG_5V on TOP (solid shape): 199.81,40.19 199.81,39.32 199.67,39.18 199.01,39.18 198.94,39.25 198.94,40.08 199.21,40.34 199.66,40.34
UG_5V on IN2 (solid shape): 208.92,50.28 208.92,49.2 208.66,48.95 207.96,48.95 207.77,49.14 207.77,50.28 207.9,50.41 208.79,50.41
UG_5V on IN2 (solid shape): 199.96,40.19 200.53,40.19 200.66,40.06 200.66,39.3 200.53,39.17 199.39,39.17 199.26,39.3 199.26,40.19 199.46,40.38 199.77,40.38
UG_+1.05VSP on TOP (solid shape): 175.13,95.24 175.13,95.11 175.07,95.05 174.37,95.05 174.12,94.8 173.23,94.8 173.1,94.92 173.1,95.18 173.23,95.3 175.07,95.3
UG_+1.05VSP on TOP (solid shape): 162.84,93.63 162.84,92.92 162.69,92.76 161.88,92.76 161.74,92.91 161.74,93.67 161.89,93.82 162.66,93.82
UG_+1.05VSP on IN2 (solid shape): 162.75,94.03 162.75,92.95 162.63,92.83 161.93,92.83 161.74,93.02 161.74,93.91 161.93,94.1 162.69,94.1
UG_+1.05VSP on IN2 (solid shape): 174.12,95.11 174.12,94.92 173.99,94.8 173.48,94.8 172.98,94.29 171.9,94.29 171.64,94.54 171.64,95.11 171.83,95.3 173.93,95.3
UGATE1 on BOTTOM (solid shape): 130.94,130.99 130.94,129.97 130.81,129.85 129.86,129.85 129.61,130.1 129.61,130.93 129.86,131.18 130.75,131.18
UGATE1 on BOTTOM (solid shape): 125.8,142.06 125.81,142.04 125.81,141.26 125.93,141.13 126.11,140.96 126.11,140.13 125.99,140.01 125.86,140.01 125.69,140.18 125.69,140.2 125.69,140.29 125.67,140.38 125.67,140.7 125.67,140.71 125.69,140.83 125.67,140.96 125.67,140.97 125.67,141.01 125.59,141.09 125.59,142.05 125.65,142.11 125.74,142.11
UGATE1 on IN4 (solid shape): 130.56,132.26 130.56,130.17 130.3,129.91 129.73,129.91 129.54,130.1 129.54,132.2 129.8,132.45 130.37,132.45
UGATE1 on IN4 (solid shape): 127.19,139.94 127.19,139.63 126.81,139.25 126.43,139.25 126.11,139.56 126.11,139.75 125.69,140.18 125.69,140.2 125.69,140.29 125.67,140.38 125.67,140.7 125.67,140.71 125.69,140.82 125.68,140.93 125.67,140.96 125.8,141.09 126.05,141.09
UGATE1_VGA on BOTTOM (solid shape): 16.89,160.77 16.89,160.45 16.45,160.01 15.56,160.01 15.37,160.2 15.37,161.03 15.56,161.22 16.45,161.22
UGATE1_VGA on IN2 (solid shape): 16.7,162.61 16.7,160.52 16.23,160.04 15.4,160.04 15.24,160.2 15.24,162.61 15.46,162.83 16.48,162.83
UGATE1_VGA on IN2 (solid shape): 27.9,151.36 27.9,150.64 27.55,150.29 25.43,150.29 25.34,150.38 25.34,151.12 25.47,151.25 26.61,151.25 26.86,151.5 27.75,151.5
UGATE2 on BOTTOM (solid shape): 112.84,131.05 112.84,128.7 112.66,128.52 112.32,128.52 112.14,128.7 112.14,130.99 112.33,131.18 112.71,131.18
UGATE2 on BOTTOM (solid shape): 123.51,142.74 123.51,142.61 123.45,142.55 122.75,142.55 122.72,142.52 122.7,142.52 122.54,142.45 122.47,142.29 122.47,142.27 122.32,142.12 122.29,142.12 122.2,142.13 122.1,142.11 122.09,142.1 121.54,142.1 121.41,142.23 121.41,142.48 121.54,142.61 122.43,142.61 122.62,142.8 123.45,142.8
UGATE2 on IN2 (solid shape): 113.1,130.55 113.1,128.77 112.84,128.51 112.27,128.51 112.02,128.77 112.02,130.42 112.27,130.67 112.97,130.67
UGATE2 on IN2 (solid shape): 122.49,142.48 122.49,142.29 122.32,142.12 122.29,142.12 122.2,142.13 122.1,142.11 122.09,142.1 121.99,142.1 121.48,141.6 121.48,141.53 120.84,140.9 120.46,140.9 120.14,141.21 120.14,141.53 121.22,142.61 122.37,142.61
UGATE2_VGA on TOP (solid shape): 21.53,152.26 21.53,151.96 21.89,151.6 21.89,150.72 21.85,150.68 21.72,150.68 21.66,150.74 21.66,151.56 21.61,151.61 21.61,151.66 21.54,151.74 21.45,151.82 20.64,151.82 20.45,152.01 20.45,152.2 20.64,152.39 21.4,152.39
UGATE2_VGA on BOTTOM (solid shape): 10.61,157.09 10.61,155.88 10.48,155.76 9.72,155.76 9.59,155.88 9.59,157.09 9.78,157.28 10.42,157.28
UGATE2_VGA on IN2 (solid shape): 21.53,152.33 21.53,152.01 21.4,151.88 19.18,151.88 18.92,152.14 18.92,152.71 19.05,152.83 21.02,152.83
UGATE2_VGA on IN2 (solid shape): 10.65,156.04 10.65,154.6 10.48,154.42 9.72,154.42 9.59,154.55 9.59,156.07 9.7,156.19 10.51,156.19
VCORE_VDDP on BOTTOM (solid shape): 124.59,142.04 124.59,141.28 124.4,141.09 124.4,140.07 124.59,139.88 124.6,139.88 124.84,139.88 124.91,139.82 124.91,139.27 124.79,139.15 123.11,139.15 123.03,139.23 123.03,139.98 123.19,140.13 123.51,140.13 123.7,140.33 123.7,140.9 123.95,141.15 123.95,141.16 123.95,142.04 124.02,142.1 124.53,142.1
VLDOIN_1.35V on TOP (solid shape): 175.64,86.22 175.64,86.16 175.58,86.1 174.5,86.1 173.55,85.14 172.61,85.14 172.61,85.62 172.07,85.62 172.07,85.81 172.61,85.81 172.61,86.29 175.58,86.29
Z4304 on TOP (solid shape): 73.47,170.11 73.47,169.34 73.15,169.03 72.2,169.03 72.01,169.22 72.01,169.98 72.52,170.49 73.09,170.49
Z4305 on TOP (solid shape): 71.57,169.98 71.57,169.03 71.44,168.9 70.68,168.9 70.11,169.47 70.11,170.04 70.49,170.42 71.12,170.42
Z4306 on TOP (solid shape): 69.47,170.17 69.47,169.28 69.03,168.84 68.65,168.84 68.07,169.41 68.07,170.04 68.45,170.42 69.22,170.42
N992434 on TOP (solid shape): 168.04,172.04 168.04,170.98 167.72,170.66 164.63,170.66 164.52,170.77 164.52,171.96 164.85,172.29 167.79,172.29
N1003474 on TOP (solid shape): 171.69,73.47 171.69,73.27 172.26,72.7 173.48,72.7 173.6,72.58 173.6,71.72 173.52,71.65 172.13,71.65 171.9,71.88 171.9,71.89 170.86,72.93 170.86,73.58 170.93,73.66 171.5,73.66
N1003522 on TOP (solid shape): 171.91,76.55 171.91,75.26 171.79,75.14 170.88,75.14 170.21,74.46 170.21,72.21 169.07,71.07 167.82,71.07 167.6,71.29 167.6,72.67 168.68,73.75 168.68,74.5 170.62,76.44 171.52,76.44 171.71,76.63 171.83,76.63
N1009712 on TOP (solid shape): 107.32,168.52 107.32,161.25 107.09,161.03 104.17,161.03 103.82,161.37 103.82,162.61 104.65,163.44 104.65,164.33 104.33,164.65 102.17,164.65 101.86,164.96 101.86,168.33 102.36,168.84 107,168.84
N1009740 on TOP (solid shape): 104.4,164.23 104.4,163.92 103.41,162.93 103.41,160.78 103.12,160.49 101.58,160.49 101.49,160.58 101.49,162.74 101.74,162.99 102.3,162.99 102.55,163.25 102.55,164.23 102.74,164.42 104.2,164.42
N18894698 on BOTTOM (solid shape): 127.98,140.68 128.58,140.68 129.41,139.85 129.41,139.34 129.34,139.27 128.79,139.27 128.73,139.2 127.62,139.2 127.51,139.31 127.51,140.26 126.38,141.39 126.38,142.05 126.44,142.11 126.55,142.11
N19359966 on TOP (solid shape): 200.06,43.42 200.06,42.79 200,42.73 197.84,42.73 197.78,42.79 197.78,43.42 197.84,43.49 200,43.49
N19360218 on TOP (solid shape): 200.15,33.32 200.15,32.67 200.07,32.59 197.98,32.59 197.94,32.63 197.94,33.32 197.99,33.37 200.11,33.37
N48711348 on BOTTOM (solid shape): 119.95,143.12 119.95,141.15 119.89,141.09 119.25,141.09 119.19,141.15 119.19,143.18 119.25,143.25 119.83,143.25
N53085144 on TOP (solid shape): 173.61,90.29 173.61,89.21 173.42,89.02 173.42,88.45 173.29,88.32 172.53,88.32 172.47,88.38 172.47,90.22 172.59,90.35 173.55,90.35
N85751870 on TOP (solid shape): 173.42,93.91 173.42,92.51 173.36,92.45 172.72,92.45 172.66,92.51 172.66,93.59 172.53,93.72 172.02,93.72 171.96,93.78 171.96,94.35 172.02,94.41 172.91,94.41

Small or netless copper shapes (teardrops, artwork), in the pictures only: 24 on TOP, 329 on BOTTOM

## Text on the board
Ref Des/Silkscreen Bottom: H14 | VOLTAGE | DIMM A | DDR3L | LOW | DIMM B | WLAN | WWAN | LABEL
User.Comments: LA9932P | 2014-07-04 | 2013-07-04 | VAL91 | Win
Ref Des/Silkscreen Top: H18 | H19 | H22 | SNIFFER | 1 | MEDIA | USH | KB | LED | TP
BODY_CENTER: 5 / 5.5
COMPVAL_TYPE_TOP: FIGURE | SIZE | 8.0 | 10.0 | 22.0 | 24.0 | 28.0 | 31.0 | 35.0 | 39.0 | 91.0 | 118.0 | 126.0 | 130.0 | 150.0 | 26.0 | 37.0 | 40.0 | 43.0 | 47.0 | 51.0 | 63.0 | 79.0 | 45.0x37.0 | 49.0x33.0 | 55.0x24.0 | 55.0x31.0 | 63.0x35.0 | 69.0x20.0 | 71.0x31.0 | 75.0x37.0 | 83.0x31.0 | 94.0x39.0 | 98.0x39.0 | 102.0x31.0 | 112.0x39.0 | 118.0x33.0 | 67.0x43.0 | 122.0x83.0 | DRILL CHART: TOP to BOTTOM | ALL UNITS ARE IN MILS | PLATED | NON-PLATED | QTY | 6595 | 733 | 19 | 31 | 9 | 18 | 13 | 2 | 8 | 1 | 4 | 5 | 7
User.20: GND | +5V_ALW | +GPU_CORE | +1.35V_MEM_GFX | +PWR_SRC | +VGA_PCIE | +VCC_CORE | +1.35V_MEM | +DOCK_PWR_BAR | +3.3V_RUN | +3.3V_ALW | GNDA | +1.05V_RUN | +1.05V_M
